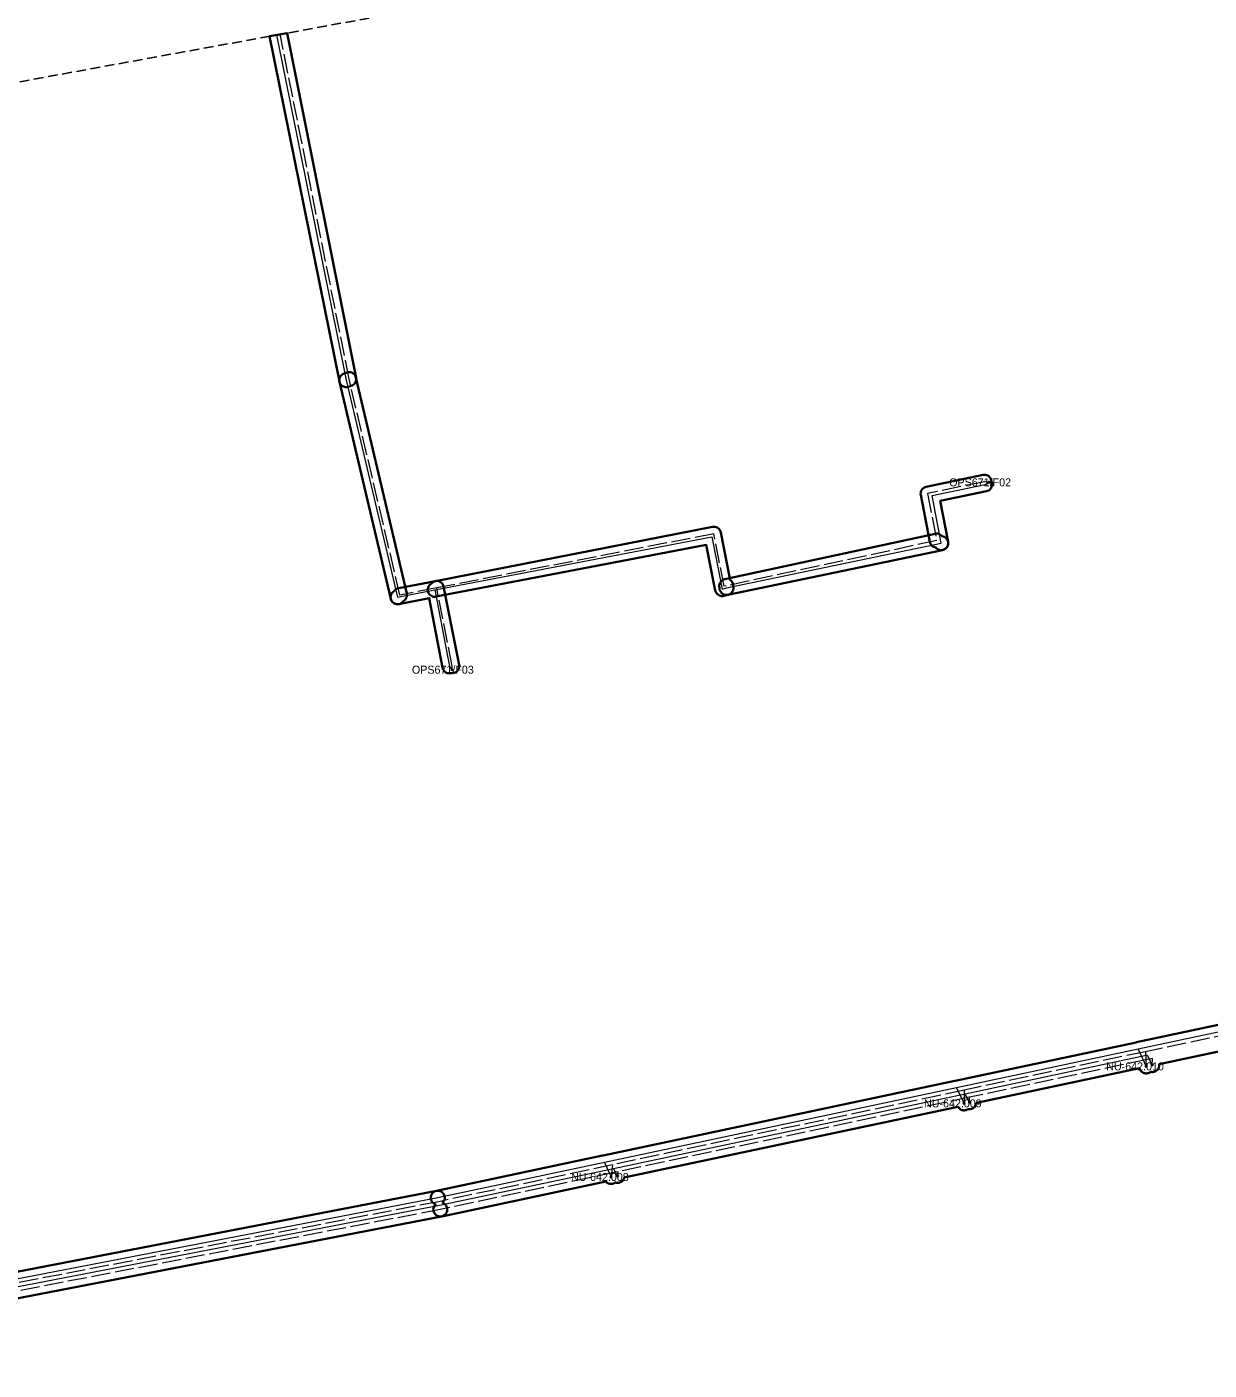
# Model space of a CAD drawing. Extents: x -452602 to -451136, y -1100088 to -1099653.
# Drawn here: x -452196.4 to -452078.2, y -1099974.7 to -1099840.4 of the extents above; entities that cross this region are included whole.
import ezdxf

# ---------------------------------------------------------------- set-up
doc = ezdxf.new("R2010")
doc.units = 0
doc.header["$LTSCALE"] = 0.32
doc.header["$PDMODE"] = 32
doc.header["$PDSIZE"] = 0.16
doc.linetypes.add('LONG_DASHED', pattern=[7.5, 6, -1.5])
doc.linetypes.add('MEDIUM_DASHED', pattern=[4.5, 3, -1.5])
for name, color, linetype, lineweight in [('2', 7, 'Continuous', 13), ('62', 7, 'MEDIUM_DASHED', 25), ('8', 7, 'Continuous', 35)]:
    doc.layers.add(name, color=color, linetype=linetype, lineweight=lineweight)
doc.layers.add('4', color=7, linetype='Continuous')

msp = doc.modelspace()

# ---------------------------------------------------------------- linework, layer by layer
at = {"layer": '2'}
for p, q in [((-452171.464, -1099841.192), (-452164.497, -1099875.71)), ((-452164.497, -1099875.71), (-452159.358, -1099897.408)), ((-452100.593, -1099886.131), (-452100.186, -1099885.926)), ((-452126.468, -1099896.487), (-452104.991, -1099892.005)), ((-452159.358, -1099897.408), (-452155.635, -1099896.666)), ((-452155.635, -1099896.666), (-452154.177, -1099904.324)), ((-452154.177, -1099904.324), (-452153.923, -1099904.658)), ((-452085.3, -1099942.603), (-452103.457, -1099946.456)), ((-452085.299, -1099942.603), (-452084.48, -1099944.326)), ((-452084.365, -1099943.222), (-452083.876, -1099944.193)), ((-452103.457, -1099946.456), (-452138.678, -1099953.929)), ((-452103.457, -1099946.456), (-452102.705, -1099948.025)), ((-452102.601, -1099947.092), (-452137.772, -1099954.554)), ((-452102.15, -1099947.898), (-452102.601, -1099947.092)), ((-452138.678, -1099953.929), (-452155.333, -1099957.462)), ((-452137.772, -1099954.554), (-452155.173, -1099958.246)), ((-452138.678, -1099953.929), (-452138.012, -1099955.383)), ((-452137.772, -1099954.554), (-452137.356, -1099955.271)), ((-452155.333, -1099957.462), (-452222.207, -1099970.354)), ((-452155.173, -1099958.246), (-452222.058, -1099971.14))]:
    msp.add_line(p, q, dxfattribs=at)
at = {"layer": '2', "linetype": 'LONG_DASHED'}
for p, q in [((-452164.2, -1099875.601), (-452171.099, -1099841.125)), ((-452159.125, -1099897.195), (-452164.2, -1099875.601)), ((-452100.186, -1099885.926), (-452100.657, -1099885.861)), ((-452105.435, -1099891.751), (-452126.482, -1099896.276)), ((-452155.444, -1099896.48), (-452159.125, -1099897.195)), ((-452153.891, -1099904.293), (-452155.444, -1099896.48)), ((-452153.923, -1099904.658), (-452153.891, -1099904.293)), ((-452084.557, -1099942.854), (-452102.685, -1099946.701)), ((-452084.556, -1099942.855), (-452084.48, -1099944.326)), ((-452083.876, -1099944.193), (-452083.851, -1099943.522)), ((-452102.685, -1099946.701), (-452137.855, -1099954.163)), ((-452102.685, -1099946.701), (-452102.705, -1099948.025)), ((-452102.148, -1099947.405), (-452137.284, -1099954.86)), ((-452102.15, -1099947.898), (-452102.148, -1099947.405)), ((-452137.855, -1099954.163), (-452155.248, -1099957.853)), ((-452137.855, -1099954.162), (-452138.012, -1099955.383)), ((-452137.356, -1099955.271), (-452137.284, -1099954.86)), ((-452155.248, -1099957.853), (-452222.134, -1099970.747)), ((-452155.097, -1099958.639), (-452221.983, -1099971.532))]:
    msp.add_line(p, q, dxfattribs=at)
for points in [[(-452100.657, -1099885.861), (-452106.346, -1099887.053), (-452105.435, -1099891.751)], [(-452126.482, -1099896.276), (-452126.68, -1099896.315), (-452127.725, -1099891.063), (-452155.444, -1099896.48)], [(-452056.916, -1099947.815), (-452056.936, -1099947.728), (-452059.373, -1099937.511), (-452084.557, -1099942.854)], [(-452083.851, -1099943.522), (-452084.391, -1099943.637), (-452102.148, -1099947.405)], [(-452137.284, -1099954.86), (-452137.689, -1099954.946), (-452155.097, -1099958.639)]]:
    msp.add_lwpolyline(points, dxfattribs=at)
at = {"layer": '2'}
for points in [[(-452104.991, -1099892.005), (-452105.896, -1099887.243), (-452100.593, -1099886.131)], [(-452155.635, -1099896.666), (-452127.933, -1099891.358), (-452126.892, -1099896.593), (-452126.468, -1099896.487)], [(-452056.527, -1099947.721), (-452056.548, -1099947.635), (-452059.074, -1099937.039), (-452085.3, -1099942.603)], [(-452084.365, -1099943.222), (-452084.474, -1099943.245), (-452102.601, -1099947.092)]]:
    msp.add_lwpolyline(points, dxfattribs=at)
at = {"layer": '4'}
for p in [(-452100.186, -1099885.926), (-452153.923, -1099904.658), (-452084.48, -1099944.326), (-452083.876, -1099944.193), (-452102.705, -1099948.025), (-452102.15, -1099947.898), (-452138.012, -1099955.383), (-452137.356, -1099955.271)]:
    msp.add_point(p, dxfattribs=at)
at = {"layer": '62'}
msp.add_lwpolyline([(-451137.485, -1099816.961), (-452572.169, -1100088.267), (-452602.314, -1099919.678), (-451137.485, -1099652.838), (-451136.368, -1099701.963)], close=True, dxfattribs=at)
at = {"layer": '8'}
for points in [[(-452164.441, -1099876.408), (-452164.553, -1099876.408), (-452164.665, -1099876.39), (-452164.772, -1099876.354), (-452164.872, -1099876.301), (-452164.962, -1099876.233), (-452165.04, -1099876.152), (-452165.104, -1099876.059), (-452165.152, -1099875.957), (-452165.183, -1099875.848), (-452172.153, -1099841.317), (-452170.41, -1099841), (-452163.514, -1099875.464), (-452163.501, -1099875.578), (-452163.506, -1099875.693), (-452163.531, -1099875.805), (-452163.573, -1099875.912), (-452163.632, -1099876.01), (-452163.707, -1099876.098), (-452163.795, -1099876.172), (-452163.894, -1099876.23), (-452164.001, -1099876.272), (-452164.113, -1099876.296), (-452164.215, -1099876.351), (-452164.326, -1099876.389)], [(-452159.303, -1099898.105), (-452159.413, -1099898.106), (-452159.522, -1099898.089), (-452159.626, -1099898.054), (-452159.725, -1099898.004), (-452159.814, -1099897.94), (-452159.892, -1099897.861), (-452159.956, -1099897.772), (-452160.006, -1099897.674), (-452160.04, -1099897.569), (-452165.178, -1099875.871), (-452165.195, -1099875.756), (-452165.193, -1099875.64), (-452165.172, -1099875.526), (-452165.132, -1099875.417), (-452165.075, -1099875.316), (-452165.002, -1099875.225), (-452164.915, -1099875.149), (-452164.816, -1099875.087), (-452164.709, -1099875.043), (-452164.595, -1099875.017), (-452164.497, -1099874.961), (-452164.39, -1099874.922), (-452164.279, -1099874.9), (-452164.166, -1099874.897), (-452164.053, -1099874.912), (-452163.945, -1099874.944), (-452163.843, -1099874.994), (-452163.751, -1099875.06), (-452163.67, -1099875.14), (-452163.604, -1099875.231), (-452163.553, -1099875.333), (-452163.519, -1099875.441), (-452158.443, -1099897.035), (-452158.426, -1099897.146), (-452158.428, -1099897.259), (-452158.447, -1099897.37), (-452158.484, -1099897.477), (-452158.538, -1099897.576), (-452158.607, -1099897.666), (-452158.689, -1099897.743), (-452158.783, -1099897.806), (-452158.848, -1099897.886), (-452158.924, -1099897.956), (-452159.009, -1099898.014), (-452159.102, -1099898.059), (-452159.201, -1099898.09)], [(-452104.935, -1099892.703), (-452105.048, -1099892.703), (-452105.16, -1099892.684), (-452105.268, -1099892.648), (-452105.368, -1099892.595), (-452105.458, -1099892.526), (-452105.536, -1099892.444), (-452105.642, -1099892.42), (-452105.742, -1099892.38), (-452105.835, -1099892.326), (-452105.919, -1099892.258), (-452105.991, -1099892.177), (-452106.05, -1099892.087), (-452106.094, -1099891.988), (-452106.123, -1099891.884), (-452107.033, -1099887.186), (-452107.046, -1099887.066), (-452107.038, -1099886.945), (-452107.009, -1099886.828), (-452106.96, -1099886.717), (-452106.893, -1099886.616), (-452106.81, -1099886.529), (-452106.713, -1099886.457), (-452106.605, -1099886.402), (-452106.489, -1099886.368), (-452100.8, -1099885.176), (-452100.681, -1099885.163), (-452100.56, -1099885.171), (-452100.443, -1099885.199), (-452100.332, -1099885.247), (-452100.231, -1099885.313), (-452100.143, -1099885.395), (-452100.07, -1099885.491), (-452100.015, -1099885.599), (-452099.98, -1099885.714), (-452099.964, -1099885.834), (-452099.924, -1099885.941), (-452099.902, -1099886.053), (-452099.898, -1099886.168), (-452099.913, -1099886.281), (-452099.947, -1099886.39), (-452099.998, -1099886.493), (-452100.064, -1099886.585), (-452100.145, -1099886.666), (-452100.238, -1099886.733), (-452100.34, -1099886.783), (-452100.45, -1099886.816), (-452105.08, -1099887.787), (-452104.303, -1099891.874), (-452104.291, -1099891.991), (-452104.299, -1099892.108), (-452104.325, -1099892.223), (-452104.371, -1099892.331), (-452104.434, -1099892.43), (-452104.513, -1099892.517), (-452104.605, -1099892.589), (-452104.708, -1099892.646), (-452104.819, -1099892.684)], [(-452127.039, -1099890.927), (-452126.09, -1099895.696), (-452126.006, -1099895.762), (-452125.934, -1099895.84), (-452125.874, -1099895.929), (-452125.828, -1099896.025), (-452125.798, -1099896.127), (-452125.783, -1099896.232), (-452125.784, -1099896.339), (-452125.769, -1099896.457), (-452125.774, -1099896.577), (-452125.8, -1099896.693), (-452125.844, -1099896.804), (-452125.908, -1099896.906), (-452125.987, -1099896.995), (-452126.081, -1099897.07), (-452126.185, -1099897.127), (-452126.299, -1099897.166), (-452126.722, -1099897.272), (-452126.834, -1099897.291), (-452126.947, -1099897.291), (-452127.059, -1099897.273), (-452127.166, -1099897.237), (-452127.266, -1099897.184), (-452127.357, -1099897.116), (-452127.435, -1099897.034), (-452127.499, -1099896.941), (-452127.547, -1099896.838), (-452127.578, -1099896.73), (-452128.484, -1099892.176), (-452155.504, -1099897.354), (-452155.624, -1099897.366), (-452155.744, -1099897.357), (-452155.861, -1099897.328), (-452155.972, -1099897.28), (-452156.072, -1099897.213), (-452156.159, -1099897.13), (-452156.231, -1099897.033), (-452156.285, -1099896.925), (-452156.32, -1099896.81), (-452156.335, -1099896.69), (-452156.328, -1099896.57), (-452156.302, -1099896.452), (-452156.255, -1099896.341), (-452156.19, -1099896.239), (-452156.108, -1099896.15), (-452156.013, -1099896.077), (-452155.946, -1099895.995), (-452155.866, -1099895.924), (-452155.777, -1099895.866), (-452155.681, -1099895.822), (-452155.578, -1099895.793), (-452127.859, -1099890.376), (-452127.738, -1099890.363), (-452127.617, -1099890.372), (-452127.499, -1099890.401), (-452127.387, -1099890.45), (-452127.286, -1099890.518), (-452127.199, -1099890.602), (-452127.126, -1099890.701), (-452127.073, -1099890.81)], [(-452126.413, -1099897.185), (-452126.534, -1099897.184), (-452126.654, -1099897.162), (-452126.768, -1099897.12), (-452126.873, -1099897.059), (-452126.965, -1099896.98), (-452127.043, -1099896.887), (-452127.104, -1099896.782), (-452127.145, -1099896.667), (-452127.166, -1099896.548), (-452127.166, -1099896.426), (-452127.181, -1099896.317), (-452127.179, -1099896.207), (-452127.159, -1099896.098), (-452127.123, -1099895.994), (-452127.071, -1099895.897), (-452127.004, -1099895.809), (-452126.924, -1099895.733), (-452126.834, -1099895.67), (-452126.734, -1099895.623), (-452126.629, -1099895.591), (-452105.582, -1099891.067), (-452105.474, -1099891.052), (-452105.364, -1099891.055), (-452105.256, -1099891.075), (-452105.152, -1099891.111), (-452105.055, -1099891.163), (-452104.968, -1099891.23), (-452104.892, -1099891.31), (-452104.779, -1099891.334), (-452104.671, -1099891.377), (-452104.572, -1099891.437), (-452104.485, -1099891.513), (-452104.411, -1099891.602), (-452104.352, -1099891.702), (-452104.311, -1099891.81), (-452104.289, -1099891.923), (-452104.285, -1099892.039), (-452104.3, -1099892.154), (-452104.334, -1099892.265), (-452104.386, -1099892.368), (-452104.454, -1099892.462), (-452104.537, -1099892.543), (-452104.632, -1099892.609), (-452104.737, -1099892.659), (-452104.848, -1099892.69), (-452126.325, -1099897.172), (-452126.339, -1099897.175)], [(-452154.758, -1099896.344), (-452153.204, -1099904.156), (-452153.191, -1099904.272), (-452153.197, -1099904.388), (-452153.223, -1099904.502), (-452153.267, -1099904.61), (-452153.328, -1099904.709), (-452153.405, -1099904.797), (-452153.495, -1099904.87), (-452153.597, -1099904.928), (-452153.706, -1099904.968), (-452153.821, -1099904.989), (-452153.937, -1099904.991), (-452154.055, -1099905.022), (-452154.176, -1099905.032), (-452154.298, -1099905.022), (-452154.415, -1099904.99), (-452154.525, -1099904.938), (-452154.625, -1099904.869), (-452154.711, -1099904.783), (-452154.781, -1099904.683), (-452154.832, -1099904.573), (-452154.864, -1099904.455), (-452156.19, -1099897.49), (-452159.222, -1099898.094), (-452159.337, -1099898.108), (-452159.454, -1099898.102), (-452159.568, -1099898.077), (-452159.675, -1099898.033), (-452159.775, -1099897.972), (-452159.863, -1099897.895), (-452159.936, -1099897.805), (-452159.994, -1099897.704), (-452160.035, -1099897.595), (-452160.056, -1099897.48), (-452160.059, -1099897.364), (-452160.042, -1099897.249), (-452160.006, -1099897.138), (-452159.952, -1099897.035), (-452159.882, -1099896.942), (-452159.798, -1099896.861), (-452159.701, -1099896.796), (-452159.632, -1099896.712), (-452159.552, -1099896.64), (-452159.461, -1099896.581), (-452159.362, -1099896.537), (-452159.258, -1099896.508), (-452155.578, -1099895.793), (-452155.457, -1099895.78), (-452155.335, -1099895.789), (-452155.217, -1099895.818), (-452155.106, -1099895.867), (-452155.005, -1099895.935), (-452154.917, -1099896.019), (-452154.845, -1099896.118), (-452154.792, -1099896.227)]]:
    msp.add_lwpolyline(points, close=True, dxfattribs=at)
for points in [[(-452138.54, -1099955.842), (-452154.937, -1099959.321), (-452154.953, -1099959.324), (-452155.027, -1099959.334), (-452155.142, -1099959.334), (-452155.255, -1099959.315), (-452155.364, -1099959.277), (-452155.466, -1099959.223), (-452155.556, -1099959.152), (-452155.635, -1099959.067), (-452155.698, -1099958.971), (-452155.744, -1099958.866), (-452155.773, -1099958.754), (-452155.783, -1099958.639), (-452155.774, -1099958.524), (-452155.747, -1099958.413), (-452155.701, -1099958.307), (-452155.638, -1099958.21), (-452155.561, -1099958.125), (-452155.672, -1099958.076), (-452155.773, -1099958.008), (-452155.861, -1099957.924), (-452155.932, -1099957.826), (-452155.986, -1099957.718), (-452156.02, -1099957.601), (-452156.034, -1099957.481), (-452156.027, -1099957.359), (-452155.998, -1099957.241), (-452155.95, -1099957.13), (-452155.884, -1099957.029), (-452155.8, -1099956.94), (-452155.703, -1099956.868), (-452155.595, -1099956.813), (-452155.479, -1099956.778), (-452138.86, -1099953.252), (-452138.844, -1099953.249), (-452138.824, -1099953.244), (-452138.819, -1099953.243), (-452138.815, -1099953.242), (-452138.811, -1099953.241), (-452103.638, -1099945.779), (-452103.627, -1099945.776), (-452103.602, -1099945.771), (-452085.481, -1099941.927), (-452085.475, -1099941.925), (-452085.445, -1099941.918), (-452059.219, -1099936.354)], [(-452060.492, -1099939.282), (-452083.172, -1099944.094), (-452083.177, -1099944.219), (-452083.178, -1099944.239), (-452083.182, -1099944.284), (-452083.19, -1099944.329), (-452083.2, -1099944.374), (-452083.213, -1099944.418), (-452083.229, -1099944.461), (-452083.248, -1099944.502), (-452083.27, -1099944.543), (-452083.294, -1099944.582), (-452083.321, -1099944.619), (-452083.35, -1099944.654), (-452083.381, -1099944.688), (-452083.415, -1099944.719), (-452083.45, -1099944.748), (-452083.487, -1099944.775), (-452083.526, -1099944.799), (-452083.567, -1099944.82), (-452083.608, -1099944.839), (-452083.651, -1099944.856), (-452083.695, -1099944.869), (-452083.74, -1099944.879), (-452083.785, -1099944.887), (-452083.83, -1099944.891), (-452083.876, -1099944.893), (-452083.922, -1099944.891), (-452083.968, -1099944.887), (-452084.013, -1099944.879), (-452084.042, -1099944.872), (-452084.054, -1099944.881), (-452084.091, -1099944.908), (-452084.13, -1099944.932), (-452084.17, -1099944.954), (-452084.212, -1099944.973), (-452084.255, -1099944.989), (-452084.299, -1099945.002), (-452084.343, -1099945.013), (-452084.388, -1099945.02), (-452084.434, -1099945.025), (-452084.48, -1099945.026), (-452084.526, -1099945.025), (-452084.571, -1099945.02), (-452084.616, -1099945.013), (-452084.661, -1099945.002), (-452084.705, -1099944.989), (-452084.748, -1099944.973), (-452084.789, -1099944.954), (-452084.83, -1099944.932), (-452084.869, -1099944.908), (-452084.906, -1099944.881), (-452084.941, -1099944.852), (-452084.975, -1099944.821), (-452085.006, -1099944.788), (-452085.035, -1099944.752), (-452085.062, -1099944.715), (-452085.086, -1099944.676), (-452085.108, -1099944.636), (-452085.112, -1099944.627), (-452085.164, -1099944.517), (-452101.454, -1099947.973), (-452101.456, -1099947.989), (-452101.463, -1099948.035), (-452101.474, -1099948.079), (-452101.487, -1099948.123)], [(-452101.503, -1099948.166), (-452101.522, -1099948.208), (-452101.544, -1099948.248), (-452101.568, -1099948.287), (-452101.594, -1099948.324), (-452101.623, -1099948.36), (-452101.655, -1099948.393), (-452101.688, -1099948.424), (-452101.724, -1099948.453), (-452101.761, -1099948.48), (-452101.8, -1099948.504), (-452101.84, -1099948.526), (-452101.882, -1099948.545), (-452101.925, -1099948.561), (-452101.969, -1099948.574), (-452102.013, -1099948.585), (-452102.058, -1099948.592), (-452102.104, -1099948.597), (-452102.15, -1099948.598), (-452102.196, -1099948.597), (-452102.241, -1099948.592), (-452102.286, -1099948.585), (-452102.316, -1099948.607), (-452102.355, -1099948.631), (-452102.395, -1099948.653), (-452102.437, -1099948.671), (-452102.48, -1099948.688), (-452102.524, -1099948.701), (-452102.568, -1099948.711), (-452102.614, -1099948.719), (-452102.659, -1099948.723), (-452102.705, -1099948.725), (-452102.751, -1099948.723), (-452102.796, -1099948.719), (-452102.842, -1099948.711), (-452102.886, -1099948.701), (-452102.93, -1099948.688), (-452102.973, -1099948.671), (-452103.015, -1099948.653), (-452103.055, -1099948.631), (-452103.094, -1099948.607), (-452103.131, -1099948.58), (-452103.166, -1099948.551), (-452103.2, -1099948.52), (-452103.231, -1099948.486), (-452103.26, -1099948.451), (-452103.287, -1099948.414), (-452103.311, -1099948.375), (-452103.315, -1099948.368), (-452136.679, -1099955.447), (-452136.68, -1099955.452), (-452136.693, -1099955.496), (-452136.71, -1099955.539), (-452136.729, -1099955.581), (-452136.75, -1099955.621), (-452136.774, -1099955.66), (-452136.801, -1099955.697), (-452136.83, -1099955.732), (-452136.861, -1099955.766), (-452136.895, -1099955.797), (-452136.93, -1099955.826), (-452136.967, -1099955.853), (-452137.006, -1099955.877), (-452137.047, -1099955.899), (-452137.088, -1099955.918), (-452137.131, -1099955.934), (-452137.175, -1099955.947), (-452137.22, -1099955.958), (-452137.265, -1099955.965), (-452137.31, -1099955.969), (-452137.356, -1099955.971), (-452137.402, -1099955.969), (-452137.448, -1099955.965), (-452137.493, -1099955.958), (-452137.538, -1099955.947), (-452137.581, -1099955.934), (-452137.585, -1099955.938), (-452137.623, -1099955.964), (-452137.662, -1099955.989), (-452137.702, -1099956.01), (-452137.744, -1099956.029), (-452137.787, -1099956.045), (-452137.83, -1099956.059), (-452137.875, -1099956.069), (-452137.92, -1099956.076), (-452137.966, -1099956.081), (-452138.012, -1099956.083), (-452138.057, -1099956.081), (-452138.103, -1099956.076), (-452138.148, -1099956.069), (-452138.193, -1099956.059), (-452138.237, -1099956.045), (-452138.279, -1099956.029), (-452138.321, -1099956.01), (-452138.362, -1099955.989), (-452138.4, -1099955.964), (-452138.438, -1099955.938), (-452138.473, -1099955.909), (-452138.506, -1099955.877), (-452138.538, -1099955.844)], [(-452222.34, -1099969.666), (-452155.466, -1099956.775), (-452155.347, -1099956.764), (-452155.227, -1099956.773), (-452155.111, -1099956.803), (-452155.002, -1099956.852), (-452154.903, -1099956.918), (-452154.816, -1099957.001), (-452154.745, -1099957.097), (-452154.691, -1099957.204), (-452154.656, -1099957.319), (-452154.642, -1099957.438), (-452154.648, -1099957.557), (-452154.674, -1099957.674), (-452154.719, -1099957.785), (-452154.783, -1099957.886), (-452154.863, -1099957.975), (-452154.758, -1099958.021), (-452154.661, -1099958.084), (-452154.576, -1099958.162), (-452154.505, -1099958.252), (-452154.45, -1099958.353), (-452154.412, -1099958.462), (-452154.392, -1099958.575), (-452154.391, -1099958.69), (-452154.409, -1099958.804), (-452154.446, -1099958.913), (-452154.5, -1099959.015), (-452154.569, -1099959.106), (-452154.653, -1099959.185), (-452154.749, -1099959.249), (-452154.853, -1099959.297), (-452154.965, -1099959.326), (-452221.851, -1099972.22)]]:
    msp.add_lwpolyline(points, dxfattribs=at)

# ---------------------------------------------------------------- texts
at = {"layer": '4'}
for s, p in [('OPS671/F02', (-452104.186, -1099886.326)), ('OPS671/F03', (-452157.923, -1099905.058)), ('NU-642.010', (-452088.48, -1099944.726)), ('NU-642.009', (-452106.705, -1099948.425)), ('NU-642.008', (-452142.012, -1099955.783))]:
    msp.add_text(s, height=0.8, dxfattribs=at).set_placement(p)

doc.saveas('drawing.dxf')
